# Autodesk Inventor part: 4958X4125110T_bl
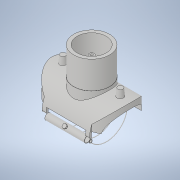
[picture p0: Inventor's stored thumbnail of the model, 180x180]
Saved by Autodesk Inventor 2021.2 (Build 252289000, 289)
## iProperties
Created: 2020-06
Part Number: 4958X4125110T_bl
Material: Generic
Description: Plasson Branch Saddle 125x110
Document SubType Name: Modeling
Designer: KIM
Density: 1 g/cm^3
Appearance: Default
Author: KIM
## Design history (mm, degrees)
derived "4958X4.ipt"
feature "Solid1::4958X4.ipt" dims "ScaleForDerivedMember" = 10
tag "TaggingFeature1"
body "Solid1"
other parameters: "d0" = 242 [user parameter], "d2" = 125 [user parameter], "d3" = 158 [user parameter], "d4" = 109 [user parameter], "d7" = 89 [user parameter], "d9" = 84 [user parameter], "d10" = 0.5 [user parameter], "d11" = 1 [user parameter], "d12" = 27.25 [user parameter], "d13" = 16 [user parameter], "d14" = 8 [user parameter], "d16" = 10 deg [user parameter], "d17" = 10 deg [user parameter], "d19" = 0 [user parameter], "d23" = 0 [user parameter], "d26" = 0 [user parameter], "d27" = 145.2 [user parameter], "d28" = 0 [user parameter], "d29" = 121 [user parameter], "d30" = 0 [user parameter], "d31" = 1 [user parameter], "d32" = 1 [user parameter], "d33" = 19.2 [user parameter], "d34" = 9.6 [user parameter], "d35" = 45 deg [user parameter], "d36" = 121 [user parameter], "d37" = 0 [user parameter], "d38" = 5 [user parameter], "d39" = 85 deg [user parameter], "d40" = 27.25 [user parameter], "d41" = 16 [user parameter], "d42" = 88 [user parameter], "d49" = 3 [user parameter], "d50" = 6 [user parameter], "d51" = 5 [user parameter], "d54" = 0 [user parameter], "d57" = 35 deg [user parameter], "d60" = 15.125 [user parameter], "d61" = 1 [user parameter], "d62" = 90 deg [user parameter], "d63" = 2 [user parameter], "d64" = 0 [user parameter], "d65" = 0 [user parameter], "d68" = 30.25 [user parameter], "d70" = 0.57711 [user parameter], "d71" = 10 deg [user parameter], "d73" = 5.775 [user parameter], "d" = 125 [user parameter], "L" = 242 [user parameter], "LS" = 84 [user parameter], "H1" = 109 [user parameter], "Dt" = 16 [user parameter], "di" = 89 [user parameter], "d72" = 16.5 [user parameter]
